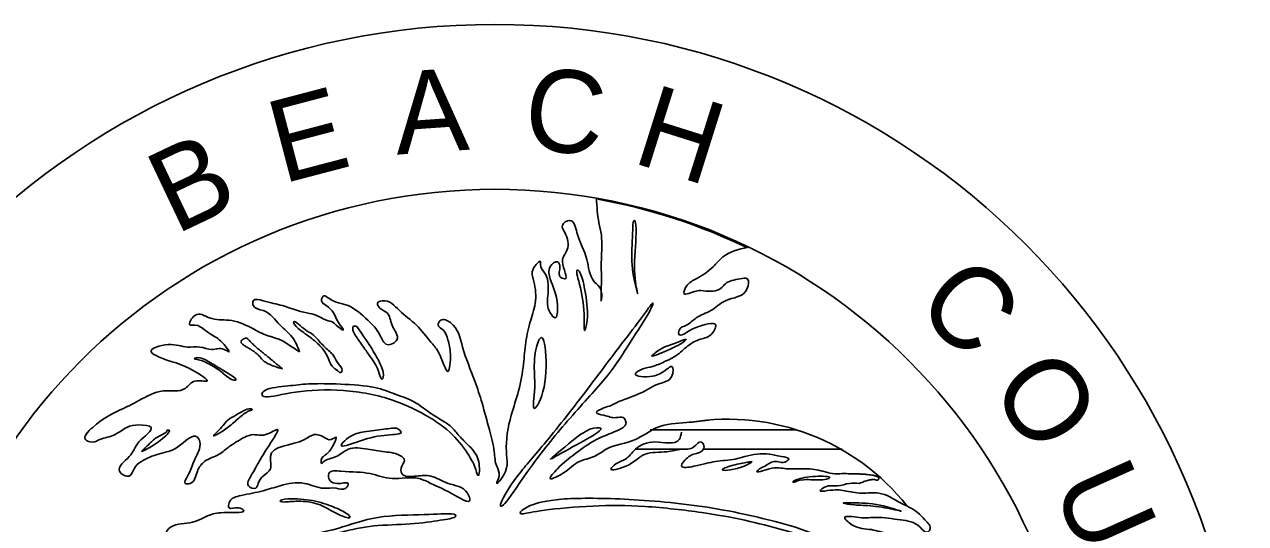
# Model space of a CAD drawing. Extents: x 783907 to 784590, y 832093 to 832609.
# Drawn here: x 784318.38 to 784322.974, y 832099.641 to 832101.518 of the extents above; entities that cross this region are included whole.
import ezdxf

# ---------------------------------------------------------------- set-up
doc = ezdxf.new("R2010")
doc.units = 0
doc.layers.add('Default', color=7, linetype='Continuous')

msp = doc.modelspace()

# ---------------------------------------------------------------- linework, layer by layer
at = {"layer": 'Default'}
for p, q in [((784320.7332, 832099.9935), (784321.2825, 832099.9935)), ((784320.6781, 832099.9203), (784320.8521, 832099.9203)), ((784320.9345, 832099.9202), (784321.4563, 832099.9203))]:
    msp.add_line(p, q, dxfattribs=at)
for radius in [2.8241, 2.2041]:
    msp.add_circle((784320.1496, 832098.6936), radius, dxfattribs=at)
for centre, radius, start, end in [((784320.1425, 832098.6922), 2.2041, 64.2352, 79.6894), ((784321.0252, 832099.1721), 0.8612, 38.42, 99.1431)]:
    msp.add_arc(centre, radius, start, end, dxfattribs=at)
for points in [[(784319.4148, 832100.2864), (784319.3874, 832100.3414), (784319.3416, 832100.3872), (784319.2776, 832100.442), (784319.2408, 832100.4605), (784319.2409, 832100.4788), (784319.2775, 832100.4786), (784319.3507, 832100.4604), (784319.4423, 832100.4329), (784319.4789, 832100.4238), (784319.5156, 832100.4056), (784319.543, 832100.3963), (784319.5521, 832100.3871), (784319.5795, 832100.3689), (784319.5614, 832100.3964), (784319.543, 832100.4329), (784319.5154, 832100.4605), (784319.4972, 832100.4787), (784319.5065, 832100.4969), (784319.5247, 832100.4879), (784319.5978, 832100.4603), (784319.6713, 832100.4055), (784319.717, 832100.3505), (784319.7445, 832100.314), (784319.781, 832100.3321), (784319.7627, 832100.3872), (784319.7444, 832100.433), (784319.717, 832100.4512), (784319.7077, 832100.4696), (784319.7261, 832100.4787), (784319.7902, 832100.4422), (784319.8543, 832100.3872), (784319.9091, 832100.323), (784319.9366, 832100.2865), (784319.9733, 832100.2133), (784319.9823, 832100.2774), (784319.9732, 832100.3323), (784319.9549, 832100.3688), (784319.9366, 832100.3872), (784319.9459, 832100.4055), (784319.9825, 832100.3964), (784320.0282, 832100.3048), (784320.0741, 832100.1767), (784320.1013, 832100.0941), (784320.129, 832099.9935), (784320.1471, 832099.911), (784320.1565, 832099.8563), (784320.1654, 832099.8196), (784320.1564, 832099.7922), (784320.1748, 832099.8104), (784320.1929, 832099.911), (784320.2112, 832100.0485), (784320.2387, 832100.1399), (784320.257, 832100.2407), (784320.2661, 832100.3231), (784320.2846, 832100.4054), (784320.3028, 832100.4788), (784320.2936, 832100.561), (784320.2936, 832100.5976), (784320.3212, 832100.6251), (784320.3211, 832100.616), (784320.3395, 832100.5793), (784320.3487, 832100.4971), (784320.3578, 832100.4329), (784320.376, 832100.4145), (784320.3851, 832100.4603), (784320.3577, 832100.5611), (784320.3577, 832100.6069), (784320.3853, 832100.6251), (784320.3943, 832100.6069), (784320.3944, 832100.5703), (784320.4126, 832100.5611), (784320.4036, 832100.6252), (784320.4219, 832100.6709), (784320.4126, 832100.735), (784320.4036, 832100.7625), (784320.4309, 832100.7807), (784320.4584, 832100.735), (784320.4952, 832100.6343), (784320.5225, 832100.5518), (784320.55, 832100.5153), (784320.55, 832100.4787), (784320.5501, 832100.5428), (784320.5501, 832100.6343), (784320.5501, 832100.7259), (784320.5409, 832100.7717), (784320.5318, 832100.8633)], [(784321.0994, 832100.6801), (784321.0076, 832100.6435), (784320.9711, 832100.6068), (784320.907, 832100.5611), (784320.8705, 832100.5336), (784320.8612, 832100.5062), (784320.907, 832100.5153), (784320.9436, 832100.5154), (784320.9986, 832100.5245), (784321.017, 832100.5427), (784321.0718, 832100.561), (784321.0992, 832100.5611), (784321.0993, 832100.5245), (784321.0169, 832100.4786), (784320.962, 832100.4421), (784320.907, 832100.4146), (784320.8704, 832100.3871), (784320.8429, 832100.3687), (784320.843, 832100.3504), (784320.8705, 832100.3597), (784320.907, 832100.378), (784320.9803, 832100.387), (784320.962, 832100.3505), (784320.9162, 832100.3322), (784320.8705, 832100.3047), (784320.8247, 832100.2681), (784320.788, 832100.2498), (784320.7422, 832100.2315), (784320.7057, 832100.2223), (784320.6782, 832100.2041), (784320.7422, 832100.1948), (784320.7697, 832100.2041), (784320.7973, 832100.2223), (784320.8154, 832100.2315), (784320.8155, 832100.1949), (784320.7698, 832100.1675), (784320.6966, 832100.1308), (784320.6048, 832100.0941), (784320.5867, 832100.0851), (784320.5592, 832100.0758), (784320.5317, 832100.0577), (784320.5591, 832100.0484), (784320.605, 832100.0392), (784320.6325, 832100.0393), (784320.6415, 832100.0118), (784320.6323, 832100.0027), (784320.5958, 832099.9843), (784320.5316, 832099.9569), (784320.4494, 832099.902), (784320.3853, 832099.8471), (784320.3579, 832099.8104), (784320.4035, 832099.8287), (784320.4676, 832099.8744), (784320.5226, 832099.8929), (784320.5683, 832099.9204), (784320.6781, 832099.9569), (784320.7605, 832100.0027), (784320.8704, 832100.0209), (784320.9529, 832100.0301)], [(784319.4971, 832099.8653), (784319.4972, 832099.8836), (784319.5156, 832099.9021), (784319.543, 832099.9385), (784319.5521, 832099.966), (784319.5338, 832099.9569), (784319.5063, 832099.966), (784319.4698, 832099.9753), (784319.4331, 832099.9569), (784319.305, 832099.8928), (784319.305, 832099.847), (784319.2774, 832099.8195), (784319.2592, 832099.7921), (784319.25, 832099.7738), (784319.2225, 832099.7829), (784319.2317, 832099.8195), (784319.2684, 832099.8836), (784319.314, 832099.9568), (784319.3325, 832099.9936), (784319.2867, 832099.9753), (784319.2409, 832099.9753), (784319.1769, 832099.9477), (784319.1493, 832099.9295), (784319.1128, 832099.902), (784319.0578, 832099.8746), (784319.0303, 832099.8379), (784319.0029, 832099.792), (784318.9846, 832099.7921), (784318.9936, 832099.8195), (784319.0212, 832099.8837), (784319.0396, 832099.9477), (784319.0303, 832099.966), (784318.9571, 832099.9293), (784318.884, 832099.902), (784318.8197, 832099.8744), (784318.7924, 832099.8471), (784318.7739, 832099.8195), (784318.7374, 832099.838), (784318.7741, 832099.8927), (784318.8107, 832099.9477), (784318.8563, 832100.0026), (784318.8106, 832100.0118), (784318.7648, 832100.0026), (784318.7191, 832099.9751), (784318.6641, 832099.9569), (784318.6368, 832099.9476), (784318.6091, 832099.9569), (784318.6366, 832100.0026), (784318.7374, 832100.0668), (784318.8106, 832100.1033), (784318.9021, 832100.1399), (784318.9845, 832100.1491), (784319.0213, 832100.1766), (784319.067, 832100.1766), (784319.0212, 832100.2133), (784318.884, 832100.2682), (784318.8563, 832100.2864), (784318.9206, 832100.314), (784318.9938, 832100.3047), (784319.0395, 832100.3047), (784319.0853, 832100.2956), (784319.131, 832100.2956), (784319.1493, 832100.2865), (784319.1311, 832100.3139), (784319.0853, 832100.3505), (784319.0577, 832100.3689), (784319.0212, 832100.3872), (784319.0029, 832100.3871), (784319.0211, 832100.4238), (784319.076, 832100.4146), (784319.1494, 832100.4056), (784319.2317, 832100.3779), (784319.2867, 832100.3506), (784319.3415, 832100.3323), (784319.3874, 832100.3048), (784319.4148, 832100.2864)], [(784320.8522, 832099.9844), (784320.8429, 832099.9568), (784320.7515, 832099.9478), (784320.6781, 832099.9203), (784320.6416, 832099.8836), (784320.6049, 832099.8653), (784320.5867, 832099.847), (784320.6417, 832099.8562), (784320.7149, 832099.902), (784320.7971, 832099.9112), (784320.8521, 832099.9203), (784320.8979, 832099.9295), (784320.9254, 832099.9477), (784320.9346, 832099.9385), (784320.9345, 832099.9202), (784320.898, 832099.902), (784320.8796, 832099.8927), (784320.8522, 832099.8563), (784320.898, 832099.8563), (784320.9802, 832099.8744), (784321.0535, 832099.8836), (784321.0902, 832099.8928), (784321.136, 832099.902), (784321.1818, 832099.902), (784321.2275, 832099.8928), (784321.2549, 832099.8835), (784321.2457, 832099.8744), (784321.2, 832099.8744), (784321.1635, 832099.8561), (784321.1451, 832099.847), (784321.1359, 832099.8379), (784321.1817, 832099.8471), (784321.2458, 832099.847), (784321.3191, 832099.8471), (784321.3831, 832099.8378), (784321.4197, 832099.8287), (784321.4563, 832099.8287)], [(784318.8565, 832098.9773), (784318.8564, 832099.0139), (784318.8655, 832099.0505), (784318.8747, 832099.0964), (784318.8747, 832099.1514), (784318.8931, 832099.1604), (784318.893, 832099.1513), (784318.9387, 832099.1787), (784318.9572, 832099.1695), (784318.9571, 832099.142), (784318.9662, 832099.1331), (784318.9754, 832099.1422), (784318.9754, 832099.1513), (784319.0303, 832099.2886), (784319.0211, 832099.2795), (784318.9938, 832099.2519), (784318.9662, 832099.2246), (784318.9388, 832099.197), (784318.9204, 832099.1788), (784318.8929, 832099.1787), (784318.8929, 832099.2245), (784318.9023, 832099.2611), (784318.9022, 832099.2885), (784318.8655, 832099.2793), (784318.829, 832099.2521), (784318.7923, 832099.2429), (784318.7558, 832099.2154), (784318.7466, 832099.2154), (784318.7191, 832099.2062), (784318.6916, 832099.1971), (784318.6733, 832099.197), (784318.6824, 832099.2336), (784318.7374, 832099.2887), (784318.7832, 832099.3436), (784318.8106, 832099.3709), (784318.829, 832099.3894), (784318.7924, 832099.3893), (784318.7558, 832099.3893), (784318.7556, 832099.3618), (784318.7192, 832099.3526), (784318.71, 832099.3527), (784318.7008, 832099.3893), (784318.7831, 832099.4535), (784318.8655, 832099.5082), (784318.9296, 832099.545), (784318.9571, 832099.554), (784318.9755, 832099.5816), (784318.9572, 832099.5815), (784318.9206, 832099.5816), (784318.9113, 832099.5998), (784318.9297, 832099.6274), (784319.012, 832099.6457), (784319.0762, 832099.6731), (784319.1401, 832099.6822), (784319.2042, 832099.6914), (784319.186, 832099.7005), (784319.1494, 832099.7006), (784319.1494, 832099.719), (784319.1951, 832099.7464), (784319.2776, 832099.7645), (784319.3416, 832099.783), (784319.4331, 832099.7922), (784319.5063, 832099.7737), (784319.5521, 832099.7737), (784319.5887, 832099.7738), (784319.5979, 832099.792), (784319.5705, 832099.7922), (784319.5248, 832099.8105), (784319.5246, 832099.8288), (784319.5705, 832099.8379), (784319.6803, 832099.8287), (784319.7628, 832099.8104), (784319.8635, 832099.8104), (784319.9092, 832099.7921), (784320.0007, 832099.7463), (784320.0556, 832099.7279), (784320.0466, 832099.7554), (784319.9733, 832099.7922), (784319.9091, 832099.8195), (784319.8542, 832099.8196), (784319.7993, 832099.8288), (784319.7994, 832099.8562), (784319.8085, 832099.8837), (784319.7994, 832099.8929), (784319.7352, 832099.911), (784319.6711, 832099.9203), (784319.5979, 832099.9202), (784319.5522, 832099.8927), (784319.5063, 832099.8744), (784319.4971, 832099.8653)], [(784321.5204, 832099.792), (784321.4838, 832099.792), (784321.438, 832099.7828), (784321.4105, 832099.783), (784321.383, 832099.7737), (784321.3738, 832099.7646), (784321.4013, 832099.7647), (784321.4653, 832099.7646), (784321.5296, 832099.7554), (784321.5937, 832099.7555), (784321.6759, 832099.7189), (784321.74, 832099.6822), (784321.7676, 832099.6549), (784321.7859, 832099.6181), (784321.7767, 832099.609), (784321.7491, 832099.6273), (784321.676, 832099.6549), (784321.5845, 832099.664), (784321.5205, 832099.6639), (784321.4655, 832099.6639), (784321.4929, 832099.6365), (784321.5662, 832099.6181), (784321.6302, 832099.5999), (784321.7127, 832099.5631), (784321.795, 832099.5082), (784321.85, 832099.4716), (784321.8775, 832099.4351), (784321.9139, 832099.3985), (784321.9141, 832099.3802), (784321.8865, 832099.4075), (784321.8042, 832099.4258), (784321.7401, 832099.4625), (784321.7036, 832099.4808), (784321.6852, 832099.4717), (784321.7585, 832099.3892), (784321.8042, 832099.3343), (784321.8682, 832099.2612), (784321.9048, 832099.1788), (784321.9324, 832099.1146), (784321.9416, 832099.0688), (784321.9414, 832099.0413), (784321.9323, 832098.9956), (784321.9139, 832098.9865), (784321.8958, 832099.0688), (784321.8042, 832099.1969), (784321.7492, 832099.2702), (784321.6577, 832099.3252), (784321.6576, 832099.316), (784321.6942, 832099.2611), (784321.7493, 832099.2061), (784321.7768, 832099.1605), (784321.7949, 832099.1238), (784321.7951, 832099.1054), (784321.7858, 832099.078), (784321.7309, 832099.1422), (784321.6759, 832099.2154), (784321.6028, 832099.2886), (784321.5478, 832099.3252), (784321.5113, 832099.3435), (784321.5296, 832099.2979), (784321.5296, 832099.2521), (784321.5569, 832099.2245), (784321.5387, 832099.188), (784321.5204, 832099.1878), (784321.4562, 832099.2703), (784321.3831, 832099.3435), (784321.3372, 832099.3984), (784321.2823, 832099.4442), (784321.2457, 832099.4533), (784321.2183, 832099.4718), (784321.2092, 832099.4352), (784321.2367, 832099.3893), (784321.2548, 832099.3528), (784321.2732, 832099.3161), (784321.2641, 832099.2887), (784321.2458, 832099.2885), (784321.2183, 832099.3344), (784321.1634, 832099.3894), (784321.0627, 832099.4808), (784321.0169, 832099.5174), (784320.9803, 832099.5267), (784320.9529, 832099.5358), (784320.9619, 832099.5083), (784321.0077, 832099.4625), (784321.0353, 832099.4351), (784321.0534, 832099.3984), (784321.0535, 832099.371), (784321.0078, 832099.3801), (784320.9527, 832099.4442), (784320.8979, 832099.4718), (784320.8155, 832099.5175)], [(784321.5204, 832099.792), (784321.4838, 832099.792), (784321.438, 832099.7828), (784321.4105, 832099.783), (784321.383, 832099.7737), (784321.3738, 832099.7646), (784321.4013, 832099.7647), (784321.4653, 832099.7646), (784321.5296, 832099.7554), (784321.5937, 832099.7555), (784321.6759, 832099.7189), (784321.74, 832099.6822), (784321.7676, 832099.6549), (784321.7859, 832099.6181), (784321.7767, 832099.609), (784321.7491, 832099.6273), (784321.676, 832099.6549), (784321.5845, 832099.664), (784321.5205, 832099.6639), (784321.4655, 832099.6639), (784321.4929, 832099.6365), (784321.5662, 832099.6181), (784321.6302, 832099.5999), (784321.7127, 832099.5631), (784321.795, 832099.5082), (784321.85, 832099.4716), (784321.8775, 832099.4351), (784321.9139, 832099.3985), (784321.9141, 832099.3802), (784321.8865, 832099.4075), (784321.8042, 832099.4258), (784321.7401, 832099.4625), (784321.7036, 832099.4808), (784321.6852, 832099.4717), (784321.7585, 832099.3892), (784321.8042, 832099.3343), (784321.8682, 832099.2612), (784321.9048, 832099.1788), (784321.9324, 832099.1146), (784321.9416, 832099.0688), (784321.9414, 832099.0413), (784321.9323, 832098.9956), (784321.9139, 832098.9865), (784321.8958, 832099.0688), (784321.8042, 832099.1969), (784321.7492, 832099.2702), (784321.6577, 832099.3252), (784321.6576, 832099.316), (784321.6942, 832099.2611), (784321.7493, 832099.2061), (784321.7768, 832099.1605), (784321.7949, 832099.1238), (784321.7951, 832099.1054), (784321.7858, 832099.078), (784321.7309, 832099.1422), (784321.6759, 832099.2154), (784321.6028, 832099.2886), (784321.5478, 832099.3252), (784321.5113, 832099.3435), (784321.5296, 832099.2979), (784321.5296, 832099.2521), (784321.5569, 832099.2245), (784321.5387, 832099.188), (784321.5204, 832099.1878), (784321.4562, 832099.2703), (784321.3831, 832099.3435), (784321.3372, 832099.3984), (784321.2823, 832099.4442), (784321.2457, 832099.4533), (784321.2183, 832099.4718), (784321.2092, 832099.4352), (784321.2367, 832099.3893), (784321.2548, 832099.3528), (784321.2732, 832099.3161), (784321.2641, 832099.2887), (784321.2458, 832099.2885), (784321.2183, 832099.3344), (784321.1634, 832099.3894), (784321.0627, 832099.4808), (784321.0169, 832099.5174), (784320.9803, 832099.5267), (784320.9529, 832099.5358), (784320.9619, 832099.5083), (784321.0077, 832099.4625), (784321.0353, 832099.4351), (784321.0534, 832099.3984), (784321.0535, 832099.371), (784321.0078, 832099.3801), (784320.9527, 832099.4442), (784320.8979, 832099.4718), (784320.8155, 832099.5175)]]:
    msp.add_spline(points, degree=3, dxfattribs=at)
for points, degree in [([(784320.6843, 832100.5153), (784320.6874, 832100.5), (784320.6872, 832100.5061), (784320.6598, 832100.6067), (784320.669, 832100.7443), (784320.669, 832100.79), (784320.6874, 832100.7716), (784320.6689, 832100.5978), (784320.6813, 832100.5306), (784320.6843, 832100.5153)], 3), ([(784320.489, 832100.3704), (784320.486, 832100.3628), (784320.4858, 832100.3689), (784320.486, 832100.4879), (784320.4492, 832100.5977), (784320.4675, 832100.5976), (784320.486, 832100.5428), (784320.5041, 832100.4146), (784320.4921, 832100.378), (784320.489, 832100.3704)], 3), ([(784320.1731, 832099.7204), (784320.1655, 832099.7006), (784320.1838, 832099.7005), (784320.2754, 832099.847), (784320.4219, 832100.03), (784320.5774, 832100.195), (784320.6416, 832100.2956), (784320.7423, 832100.4512), (784320.7515, 832100.4877), (784320.6966, 832100.4054), (784320.6233, 832100.314), (784320.495, 832100.14), (784320.3211, 832099.9202), (784320.2295, 832099.8195), (784320.1807, 832099.7403), (784320.1731, 832099.7204)], 3), ([(784319.5705, 832100.2087), (784319.5735, 832100.2102), (784319.5797, 832100.2224), (784319.5522, 832100.2498), (784319.5429, 832100.2773), (784319.5064, 832100.3047), (784319.4698, 832100.3506), (784319.4515, 832100.3597), (784319.4239, 832100.3781), (784319.3966, 832100.4055), (784319.3874, 832100.3964), (784319.4147, 832100.3688), (784319.4697, 832100.3323), (784319.5064, 832100.2955), (784319.5247, 832100.259), (784319.5338, 832100.2315), (784319.5614, 832100.2133), (784319.5674, 832100.2072), (784319.5705, 832100.2087)], 3), ([(784319.6238, 832100.3841), (784319.6193, 832100.3841), (784319.607, 832100.3781), (784319.6345, 832100.3322), (784319.662, 832100.2957), (784319.7077, 832100.2316), (784319.7169, 832100.1949), (784319.7262, 832100.1766), (784319.7352, 832100.204), (784319.7079, 832100.2682), (784319.6345, 832100.378), (784319.6284, 832100.3841), (784319.6238, 832100.3841)], 3), ([(784319.3508, 832100.2224), (784319.2959, 832100.2682), (784319.2501, 832100.3048), (784319.2225, 832100.3322), (784319.2134, 832100.3414), (784319.1859, 832100.323), (784319.2317, 832100.2955), (784319.2591, 832100.2773), (784319.2866, 832100.2408), (784319.3508, 832100.2224)], 2), ([(784320.2952, 832100.1019), (784320.2967, 832100.1187), (784320.3028, 832100.1492), (784320.2937, 832100.2499), (784320.312, 832100.3414), (784320.3395, 832100.3506), (784320.3486, 832100.1583), (784320.2936, 832100.0485), (784320.2936, 832100.0852), (784320.2952, 832100.1019)], 3), ([(784320.7423, 832100.2742), (784320.7362, 832100.2681), (784320.7424, 832100.2681), (784320.8522, 832100.314), (784320.8796, 832100.3413), (784320.8429, 832100.323), (784320.7789, 832100.3047), (784320.7484, 832100.2803), (784320.7423, 832100.2742)], 3), ([(784319.1723, 832100.1796), (784319.1768, 832100.1796), (784319.1767, 832100.1857), (784319.1493, 832100.2042), (784319.1035, 832100.2316), (784319.0578, 832100.2591), (784319.0304, 832100.2681), (784319.0121, 832100.2591), (784319.0395, 832100.2589), (784319.0943, 832100.2314), (784319.131, 832100.204), (784319.1493, 832100.1858), (784319.1677, 832100.1797), (784319.1723, 832100.1796)], 3), ([(784320.083, 832099.8272), (784320.0861, 832099.8196), (784320.0922, 832099.8195), (784320.0923, 832099.8928), (784320.0466, 832099.9385), (784320.0099, 832099.9751), (784319.9824, 832100.0119), (784319.9459, 832100.0301), (784319.8909, 832100.0668), (784319.8451, 832100.1034), (784319.7628, 832100.1308), (784319.6986, 832100.1584), (784319.543, 832100.1674), (784319.4423, 832100.1674), (784319.3782, 832100.1584), (784319.2683, 832100.1491), (784319.2683, 832100.1033), (784319.3873, 832100.14), (784319.5796, 832100.1491), (784319.7719, 832100.1125), (784319.9458, 832100.021), (784320.0191, 832099.9478), (784320.0739, 832099.8654), (784320.08, 832099.8349), (784320.083, 832099.8272)], 3), ([(784319.2363, 832100.0683), (784319.2379, 832100.0698), (784319.2318, 832100.0758), (784319.2043, 832100.0668), (784319.1767, 832100.0484), (784319.1402, 832100.03), (784319.131, 832100.0118), (784319.1036, 832099.9844), (784319.0852, 832099.966), (784319.1036, 832099.9753), (784319.1493, 832100.0028), (784319.1861, 832100.0392), (784319.2226, 832100.0667), (784319.2348, 832100.0668), (784319.2363, 832100.0683)], 3), ([(784318.9175, 832099.9919), (784318.9145, 832099.9904), (784318.9205, 832099.9844), (784318.8747, 832099.9661), (784318.8473, 832099.9386), (784318.8197, 832099.911), (784318.8197, 832099.911), (784318.8748, 832099.9387), (784318.9389, 832099.9935), (784318.9206, 832099.9934), (784318.9175, 832099.9919)], 3), ([(784319.7917, 832099.992), (784319.7872, 832099.9966), (784319.7809, 832100.0026), (784319.717, 832099.9935), (784319.6346, 832099.9843), (784319.5979, 832099.966), (784319.5705, 832099.9386), (784319.5705, 832099.9295), (784319.6071, 832099.9387), (784319.7078, 832099.9752), (784319.8085, 832099.9752), (784319.7963, 832099.9875), (784319.7917, 832099.992)], 3), ([(784320.3715, 832099.8944), (784320.3516, 832099.8776), (784320.3578, 832099.8837), (784320.495, 832099.9569), (784320.5682, 832100.0028), (784320.5225, 832100.0028), (784320.4768, 832099.9845), (784320.3913, 832099.9112), (784320.3715, 832099.8944)], 3), ([(784321.0154, 832099.8409), (784321.0047, 832099.8409), (784320.9986, 832099.8471), (784321.0626, 832099.8653), (784321.1176, 832099.8744), (784321.1176, 832099.8744), (784321.1084, 832099.8653), (784321.0627, 832099.847), (784321.0261, 832099.8409), (784321.0154, 832099.8409)], 3), ([(784321.2763, 832099.7967), (784321.2702, 832099.7952), (784321.2641, 832099.8013), (784321.3281, 832099.8195), (784321.4288, 832099.8195), (784321.3923, 832099.8011), (784321.3006, 832099.8103), (784321.2823, 832099.7982), (784321.2763, 832099.7967)], 3), ([(784321.4563, 832099.8287), (784321.5295, 832099.8286), (784321.5936, 832099.8196), (784321.5937, 832099.8013), (784321.566, 832099.8103), (784321.5204, 832099.792)], 2), ([(784319.5964, 832099.6625), (784319.6071, 832099.661), (784319.6072, 832099.6732), (784319.5522, 832099.7005), (784319.4788, 832099.7281), (784319.3782, 832099.7373), (784319.3324, 832099.7281), (784319.3508, 832099.7189), (784319.4056, 832099.728), (784319.4882, 832099.7189), (784319.5429, 832099.6822), (784319.5857, 832099.664), (784319.5964, 832099.6625)], 3), ([(784320.2463, 832099.6853), (784320.2418, 832099.6792), (784320.248, 832099.6732), (784320.312, 832099.6914), (784320.5226, 832099.7098), (784320.7057, 832099.7098), (784320.9436, 832099.6823), (784321.0901, 832099.6548), (784321.2367, 832099.6181), (784321.3831, 832099.5723), (784321.4379, 832099.5448), (784321.4653, 832099.5358), (784321.383, 832099.5906), (784321.264, 832099.6365), (784320.9529, 832099.7097), (784320.6232, 832099.7372), (784320.376, 832099.7371), (784320.2754, 832099.7097), (784320.2509, 832099.6913), (784320.2463, 832099.6853)], 3), ([(784321.4608, 832099.7174), (784321.4562, 832099.7189), (784321.4745, 832099.7188), (784321.5844, 832099.7189), (784321.6943, 832099.6822), (784321.6668, 832099.6913), (784321.5662, 832099.7096), (784321.5021, 832099.7097), (784321.4654, 832099.7159), (784321.4608, 832099.7174)], 3), ([(784319.9992, 832099.6654), (784320.0068, 832099.67), (784320.0006, 832099.6822), (784319.9001, 832099.6731), (784319.6987, 832099.6732), (784319.5614, 832099.6183), (784319.4056, 832099.5907), (784319.186, 832099.5265), (784319.1767, 832099.4991), (784319.1952, 832099.4901), (784319.2958, 832099.5175), (784319.4607, 832099.5815), (784319.5705, 832099.6091), (784319.6894, 832099.6364), (784319.8359, 832099.6366), (784319.955, 832099.6547), (784319.9916, 832099.6608), (784319.9992, 832099.6654)], 3)]:
    msp.add_open_spline(points, degree=degree, dxfattribs=at)

# ---------------------------------------------------------------- texts
for s, rotation, p in [('A', 3.9657, (784319.781, 832101.0279)), ('C', 353.2268, (784320.2478, 832101.0553)), ('E', 14.7047, (784319.3506, 832100.9181)), ('H', 342.4878, (784320.6599, 832101.0004)), ('B', 25.4436, (784318.948, 832100.7258)), ('C', 315.6405, (784321.7219, 832100.4513)), ('O', 304.9016, (784322.0056, 832100.1492)), ('U', 294.1626, (784322.2436, 832099.7829))]:
    msp.add_text(s, height=0.31, rotation=rotation, dxfattribs=at).set_placement(p)

doc.saveas('drawing.dxf')
